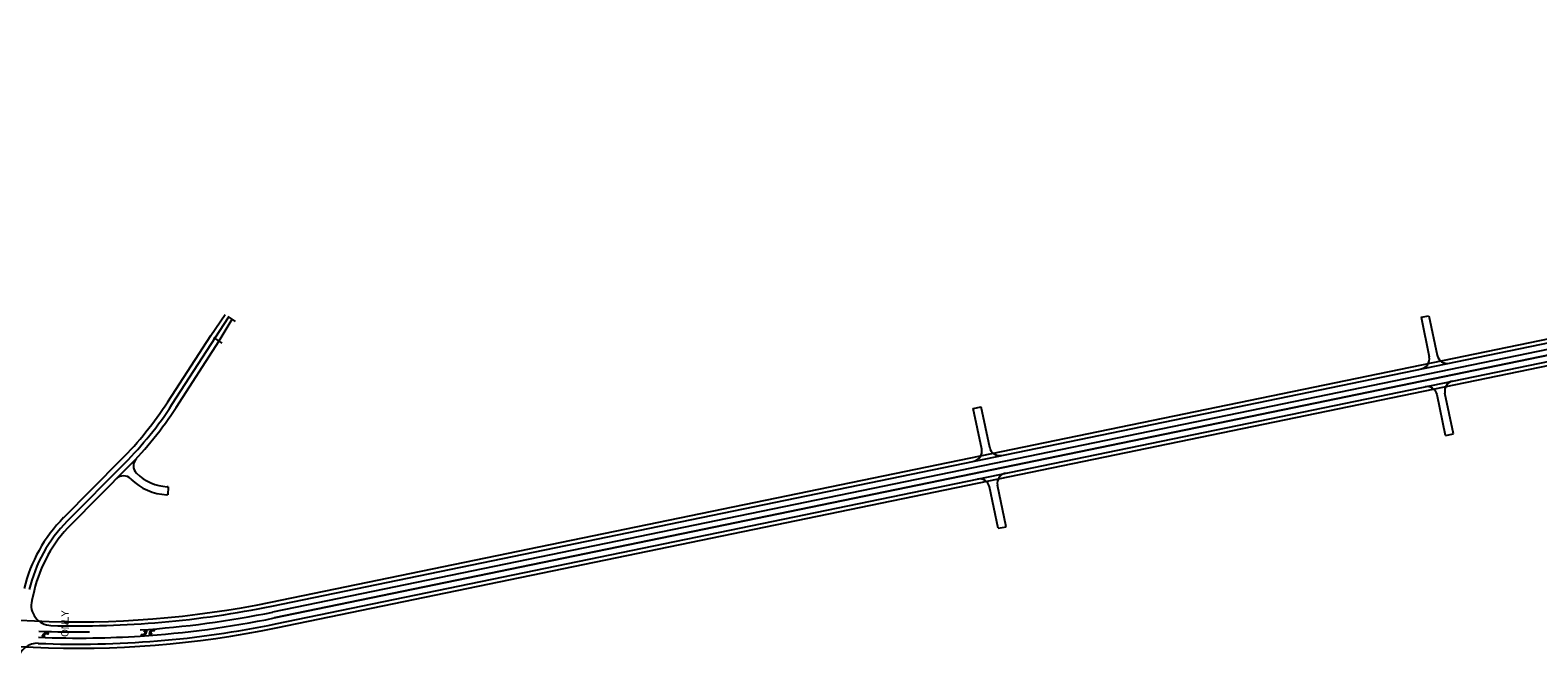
# Model space of a CAD drawing. Extents: x 979036 to 996074, y 1836928 to 1845163.
# Drawn here: x 984093 to 987063, y 1837677 to 1838917 of the extents above; entities that cross this region are included whole.
import ezdxf

# ---------------------------------------------------------------- set-up
doc = ezdxf.new("R2010")
doc.units = 0
for name, color, linetype in [('R_Proposed Road', 7, 'Continuous'), ('STRIPE_White Turn Arrow', 7, 'Continuous'), ('STRIPE_White_6in', 7, 'Continuous'), ('STRIPE_White_ONLY', 7, 'Continuous'), ('STRIPE_Yellow Dbl 6in', 7, 'Continuous'), ('STRIPE_Yellow_10_30 SKIP', 7, 'Continuous')]:
    doc.layers.add(name, color=color, linetype=linetype)

msp = doc.modelspace()

# ---------------------------------------------------------------- linework, layer by layer
at = {"layer": 'R_Proposed Road'}
for p, q in [((984567.2, 1837789.5), (990028.6, 1838916.9)), ((984577.7, 1837738.6), (990039.1, 1838866)), ((986832.7, 1838350.9), (986848.4, 1838354)), ((986832.7, 1838350.9), (986848.8, 1838272.8)), ((986848.4, 1838354), (986864.5, 1838276)), ((986880.8, 1838117.6), (986864.2, 1838198.3)), ((986896.5, 1838121), (986879.8, 1838201.6)), ((985950.8, 1838171.1), (985966.5, 1838174.3)), ((985967.4, 1838090.8), (985950.8, 1838171.1)), ((985983.1, 1838094), (985966.5, 1838174.3)), ((986880.8, 1838117.6), (986896.5, 1838121)), ((984302.4, 1838043.8), (984302.7, 1838043.5)), ((984291.1, 1838032.5), (984291.5, 1838032.1)), ((984365.1, 1838016.8), (984363.1, 1838016.9)), ((984365.1, 1838016.8), (984364.4, 1838000.9)), ((985999.6, 1837934.9), (985982.8, 1838016.4)), ((986015.3, 1837938), (985998.4, 1838019.6)), ((984364.4, 1838000.9), (984362.4, 1838001)), ((985999.6, 1837934.9), (986015.3, 1837938))]:
    msp.add_line(p, q, dxfattribs=at)
for points in [[(984482.1, 1838352.7), (984497.1, 1838342.5)], [(984454.1, 1838311.2), (984470.7, 1838300)]]:
    msp.add_lwpolyline(points, dxfattribs=at)
for centre, radius, start, end in [((986829.2, 1838268.7), 20, 281.6644, 11.6644), ((986884.1, 1838280), 20, 191.6644, 281.6644), ((986844.6, 1838194.3), 20, 11.6644, 101.6644), ((986899.4, 1838205.6), 20, 101.6644, 191.6644), ((986002.7, 1838098.1), 20, 191.6644, 281.6644), ((984316.5, 1838058), 20, 135.5655, 225.2714), ((985947.8, 1838086.8), 20, 281.6644, 11.6644), ((984277.1, 1838018.2), 20, 45.2714, 135.2714), ((984367.5, 1838108.8), 92, 225.2714, 267.2714), ((986018, 1838023.7), 20, 101.6644, 191.6644), ((984367.5, 1838108.8), 108, 225.2714, 267.2714), ((984277.4, 1838017.9), 20, 45.2713, 45.2714), ((985963.2, 1838012.3), 20, 11.6644, 101.6644), ((984186.3, 1839634.4), 1883.9, 253.1679, 281.6644), ((984186.3, 1839634.4), 1935.9, 253.1679, 281.6644)]:
    msp.add_arc(centre, radius, start, end, dxfattribs=at)
at = {"layer": 'STRIPE_White Turn Arrow'}
for points in [[(984122.1, 1837723.1), (984119.4, 1837719.7), (984116.7, 1837723.1), (984118.4, 1837723.1), (984118.5, 1837723.8), (984118.5, 1837724.3), (984118.8, 1837725.1), (984119.2, 1837726), (984119.7, 1837726.7), (984120.3, 1837727.3), (984121, 1837727.9), (984121.7, 1837728.2), (984122.5, 1837728.6), (984123.5, 1837728.7), (984124.5, 1837728.8), (984128.4, 1837728.4), (984128.1, 1837726.4), (984124.6, 1837726.7), (984123.9, 1837726.8), (984123.1, 1837726.6), (984122.3, 1837726.3), (984121.6, 1837725.8), (984121.4, 1837725.5), (984120.9, 1837725), (984120.6, 1837724.2), (984120.4, 1837723.5), (984120.4, 1837723.1)], [(984317.8, 1837730.2), (984319.6, 1837734.2), (984323, 1837731.4), (984321.3, 1837731), (984321.4, 1837730.4), (984321.5, 1837729.8), (984321.4, 1837729), (984321.2, 1837728), (984320.9, 1837727.2), (984320.4, 1837726.5), (984319.9, 1837725.8), (984319.2, 1837725.3), (984318.6, 1837724.8), (984317.7, 1837724.4), (984316.7, 1837724.1), (984312.8, 1837723.6), (984312.6, 1837725.6), (984316.2, 1837726.1), (984316.8, 1837726.2), (984317.5, 1837726.5), (984318.3, 1837727), (984318.8, 1837727.7), (984319, 1837728), (984319.3, 1837728.6), (984319.4, 1837729.4), (984319.4, 1837730.2), (984319.4, 1837730.6)], [(984332.4, 1837728.4), (984330.6, 1837724.4), (984327.2, 1837727.1), (984328.8, 1837727.5), (984328.7, 1837728.2), (984328.7, 1837728.7), (984328.7, 1837729.5), (984329, 1837730.5), (984329.3, 1837731.3), (984329.7, 1837732), (984330.3, 1837732.7), (984330.9, 1837733.2), (984331.6, 1837733.8), (984332.4, 1837734.2), (984333.4, 1837734.5), (984337.3, 1837734.9), (984337.5, 1837733), (984334, 1837732.5), (984333.3, 1837732.3), (984332.6, 1837732), (984331.9, 1837731.5), (984331.3, 1837730.9), (984331.1, 1837730.5), (984330.9, 1837729.9), (984330.7, 1837729.1), (984330.7, 1837728.3), (984330.8, 1837728)]]:
    msp.add_lwpolyline(points, close=True, dxfattribs=at)
at = {"layer": 'STRIPE_White_6in'}
for p, q in [((984568.8, 1837781.7), (990030.2, 1838909.1)), ((984576.1, 1837746.4), (990037.5, 1838873.9)), ((984448.6, 1838315.1), (984476.9, 1838356.3)), ((984465.4, 1838304.2), (984491, 1838347.2)), ((984363.9, 1838184.1), (984448.6, 1838315.1)), ((984380.7, 1838173.2), (984465.4, 1838304.2)), ((984158.9, 1837955.8), (984272.6, 1838070.5)), ((984173.2, 1837941.8), (984286.8, 1838056.5)), ((984100.7, 1837811.6), (984096.2, 1837792.6))]:
    msp.add_line(p, q, dxfattribs=at)
for centre, radius, start, end in [((983770.9, 1838567.5), 706.2, 315.2714, 327.1139), ((983770.9, 1838567.5), 726.2, 315.2714, 327.1139), ((984369.6, 1837747.2), 296.5, 135.2714, 166.5199), ((984369.6, 1837747.2), 276.5, 135.2714, 166.5199), ((984135.1, 1837783.3), 40, 166.5199, 268.413), ((984186.3, 1839634.4), 1891.9, 268.413, 281.6644), ((984186.3, 1839634.4), 1927.9, 267.7026, 281.6644), ((984107.5, 1837668.2), 40, 87.7026, 166.5199), ((984186.3, 1839634.4), 1903.9, 267.7026, 270.7121)]:
    msp.add_arc(centre, radius, start, end, dxfattribs=at)
at = {"layer": 'STRIPE_Yellow Dbl 6in'}
for p, q in [((984372.3, 1838178.7), (984484.1, 1838351.6)), ((984166, 1837948.8), (984279.7, 1838063.5))]:
    msp.add_line(p, q, dxfattribs=at)
for centre, radius, start, end in [((983770.9, 1838567.5), 716.2, 315.2714, 327.1139), ((984369.6, 1837747.2), 286.5, 135.2714, 166.5199), ((984186.3, 1839634.4), 1915.9, 267.7026, 270.9125), ((984186.3, 1839634.4), 1915.9, 270.9125, 273.7016)]:
    msp.add_arc(centre, radius, start, end, dxfattribs=at)
at = {"layer": 'STRIPE_Yellow_10_30 SKIP'}
for p, q in [((984571.3, 1837769.9), (990032.6, 1838897.4)), ((984571.3, 1837769.9), (990032.6, 1838897.4)), ((990035, 1838885.6), (984573.7, 1837758.2)), ((984573.7, 1837758.2), (990035, 1838885.6))]:
    msp.add_line(p, q, dxfattribs=at)
for radius, start in [(1903.9, 273.7215), (1903.9, 273.7215), (1915.9, 273.7016), (1915.9, 273.7016)]:
    msp.add_arc((984186.3, 1839634.4), radius, start, 281.6644, dxfattribs=at)

# ---------------------------------------------------------------- texts
at = {"layer": 'STRIPE_White_ONLY'}
msp.add_text('ONLY', height=14.4, rotation=89.4019, dxfattribs=at).set_placement((984168.4, 1837720.8))

doc.saveas('drawing.dxf')
